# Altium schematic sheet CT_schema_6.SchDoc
size 208 x 258 mm
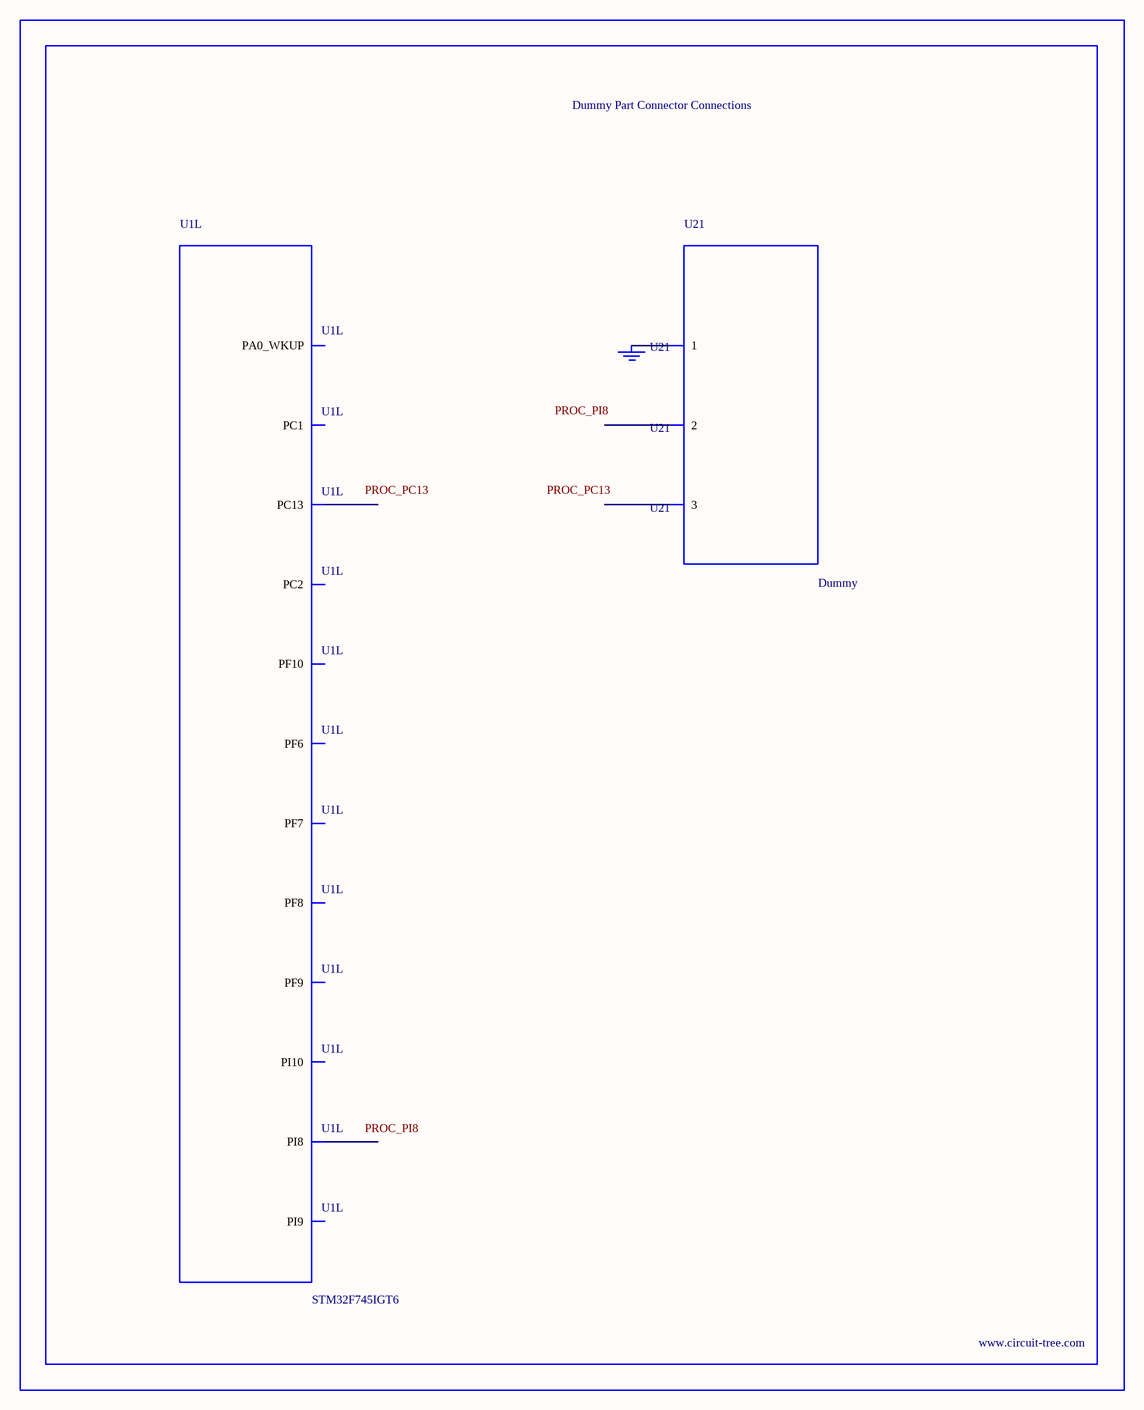
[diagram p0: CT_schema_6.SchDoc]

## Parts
BORDER5  (no value)
GND_INSTANCE_5_0  (no value)
U1  STM32F745IGT6  [LQFP176]  (part L of 12)
U21  Dummy  [DUMMY_PACKAGE_227]

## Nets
NetGND_INSTANCE_5_0_0: GND_INSTANCE_5_0.0(GND) U21.1

Not connected (* = marked no-connect by the designer): U1 7(PI8) 8(PC13) 11(PI9) 12(PI10) 24(PF6) 25(PF7) 26(PF8) 27(PF9) 28(PF10) 33(PC1) 34(PC2) 40(PA0_WKUP); U21 2 3

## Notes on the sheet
- Labels drawn without touching a wire or pin: PROC_PC13, PROC_PI8

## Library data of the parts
BORDER5 = BORDER_PAGE5
GND_INSTANCE_5_0 = GND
